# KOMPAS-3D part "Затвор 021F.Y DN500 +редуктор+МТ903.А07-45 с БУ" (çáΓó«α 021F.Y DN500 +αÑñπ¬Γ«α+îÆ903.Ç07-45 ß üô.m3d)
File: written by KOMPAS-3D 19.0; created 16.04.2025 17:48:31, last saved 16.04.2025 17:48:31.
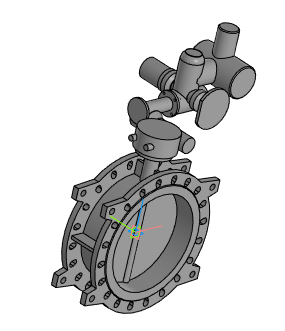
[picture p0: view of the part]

Document properties: Полное имя файла: Затвор 021F.Y DN500 +редуктор+МТ903.А07-45 с БУ.a3d

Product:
- Part/product: Затвор 021F.Y DN500 +редуктор+МТ903.А07-45 с БУ
    Масса: 339.191

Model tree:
1. Операция без истории:1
